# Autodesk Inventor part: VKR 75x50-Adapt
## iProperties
Created: 2007-05
Part Number: VKR 75x50-Adapt
Document SubType Name: Modeling
Designer: kurs1
Density: 1 g/cm^3
Author: kurs1
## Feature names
1. Extrusion1
